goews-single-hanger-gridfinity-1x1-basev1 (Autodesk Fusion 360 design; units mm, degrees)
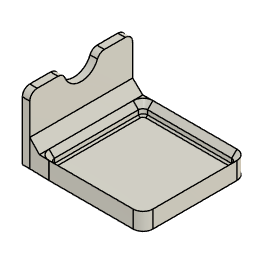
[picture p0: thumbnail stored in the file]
base_feature "Base Feature1" bodies "Single Plate Blank"
copy_paste_bodies "CutPasteBodies"
align "Align1"
align "Align2"
align "Align3"
move "Move1"
move "Move2"
sketch "Sketch1" plane through (0, 0, -202.1244) normal (0, 0, -1) x axis (1, 0, 0)
  line L1 (99.15, -20.8) -> (96.15, -20.8)
  line L2 (99.15, 20.8) -> (99.15, -20.8)
  line L3 (96.15, 20.8) -> (99.15, 20.8)
  line L4 (96.15, 15.3) -> (96.15, 20.8)
  line L5 (96.15, -15.3) -> (96.15, 15.3)
  line L6 (96.15, -20.8) -> (96.15, -15.3)
  line L7 (107.15, 21) -> (141.15, 21)
  line L8 (103.15, -17) -> (103.15, 17)
  line L9 (141.15, -21) -> (107.15, -21)
  line L10 (145.15, 17) -> (145.15, -17)
  line L11 (141.15, 18.1536) -> (107.15, 18.1536)
  line L12 (142.3036, -17) -> (142.3036, 17)
  line L13 (107.15, -18.1536) -> (141.15, -18.1536)
  line L14 (105.9964, 17) -> (105.9964, -17)
  line L15 (107.0494, 20.9987) -> (99.15, 20.8)
  line L16 (107.0494, -20.9987) -> (99.15, -20.8)
  arc A1 centre (141.15, 17) radius 4 clockwise from (141.15, 21) to (145.15, 17)
  arc A2 centre (107.15, 17) radius 4 clockwise from (103.15, 17) to (107.15, 21)
  arc A3 centre (107.15, -17) radius 4 clockwise from (107.15, -21) to (103.15, -17)
  arc A4 centre (141.15, -17) radius 4 clockwise from (145.15, -17) to (141.15, -21)
  arc A5 centre (107.15, 17) radius 1.1536 clockwise from (105.9964, 17) to (107.15, 18.1536)
  arc A6 centre (141.15, 17) radius 1.1536 clockwise from (141.15, 18.1536) to (142.3036, 17)
  arc A7 centre (141.15, -17) radius 1.1536 clockwise from (142.3036, -17) to (141.15, -18.1536)
  arc A8 centre (107.15, -17) radius 1.1536 clockwise from (107.15, -18.1536) to (105.9964, -17)
  point P4 (99.15, 20.8)
  point P28 (99.15, 20.8)
  point P29 (107.0494, 20.9987)
  point P3 (99.15, -20.8)
  point P30 (99.15, -20.8)
  point P31 (107.0494, -20.9987)
  coincident P4 P28
  coincident A2 P29
  tangent A2 L15
  coincident P3 P30
  coincident A3 P31
  tangent A3 L16
extrude "Extrude1" add sketch "Sketch1" profile of L2 A2 L8 A3 L15 L16 against normal blind 4.646 bodies "Grid"
chamfer "Chamfer1" distance 4
fillet "Fillet1" radius 3
sketch "Sketch2" plane through (0, 0, -202.1244) normal (0, 0, -1) x axis (1, 0, 0)
  line L1 (141.15, 18.1536) -> (107.15, 18.1536)
  line L2 (142.3036, -17) -> (142.3036, 17)
  line L3 (107.15, -18.1536) -> (141.15, -18.1536)
  line L4 (105.9964, 17) -> (105.9964, -17)
  line L5 (99.15, -20.8) -> (96.15, -20.8)
  line L6 (107.0494, -20.9987) -> (99.15, -20.8)
  line L7 (141.15, -21) -> (107.15, -21)
  line L8 (145.15, 17) -> (145.15, -17)
  line L9 (107.15, 21) -> (141.15, 21)
  line L10 (99.15, 20.8) -> (107.0494, 20.9987)
  line L11 (96.15, 20.8) -> (99.15, 20.8)
  line L12 (96.15, 15.3) -> (96.15, 20.8)
  line L13 (96.15, -15.3) -> (96.15, 15.3)
  line L14 (96.15, -20.8) -> (96.15, -15.3)
  arc A1 centre (107.15, 17) radius 1.1536 clockwise from (105.9964, 17) to (107.15, 18.1536)
  arc A2 centre (141.15, 17) radius 1.1536 clockwise from (141.15, 18.1536) to (142.3036, 17)
  arc A3 centre (141.15, -17) radius 1.1536 clockwise from (142.3036, -17) to (141.15, -18.1536)
  arc A4 centre (107.15, -17) radius 1.1536 clockwise from (107.15, -18.1536) to (105.9964, -17)
  arc A5 centre (107.15, -17) radius 4 clockwise from (107.15, -21) to (107.0494, -20.9987)
  arc A6 centre (141.15, -17) radius 4 clockwise from (145.15, -17) to (141.15, -21)
  arc A7 centre (141.15, 17) radius 4 clockwise from (141.15, 21) to (145.15, 17)
  arc A8 centre (107.15, 17) radius 4 clockwise from (107.0494, 20.9987) to (107.15, 21)
extrude "Extrude2" add sketch "Sketch2" along normal blind 2.354
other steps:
base_feature "Base Feature2" bodies "Grid"
named bodies: "Single Plate Blank", "Grid"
